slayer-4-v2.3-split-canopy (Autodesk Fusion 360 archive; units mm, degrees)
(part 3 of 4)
sketch "Sketch64" plane through (-29.64, 0, 0) normal (-1, 0, 0) x axis (0, -1, 0)
  line L1 (-15.4786, 27.5587) -> (-15.4786, 29.759)
  curve K1 (-15.4786, 27.5587) -> (-12.9624, 29.4655)
  curve K2 (-12.9624, 29.4655) -> (-5.541, 33.0818)
  curve K3 (-5.541, 33.0818) -> (-5, 33.1238)
  line L2 (-5, 34.5333) -> (-5, 33.1238)
  curve K4 (-5, 34.5333) -> (-5.9482, 34.4612)
  curve K5 (-5.9482, 34.4612) -> (-15.4786, 29.759)
  line L3 (0, 35) -> (0, 33.7692)
  line L4 (0, 33.7692) -> (0, 35)
  line L5 (-15.4786, 27.5587) -> (0, 30.4427)
  line L6 (0, 34.5333) -> (-5, 34.5333)
  line L7 (0, 30.4427) -> (0, 33.7692)
  point P10 (0, 35)
  point P11 (0, 35)
  point P9 (0, 33.7692)
  point P12 (0, 33.7692)
  point P3 (-15.4786, 27.5587)
  point P13 (-15.4786, 27.5587)
  point P7 (-5, 34.5333)
  point P14 (-5, 34.5333)
  point P15 (0, 34.5333)
  point P16 (0, 33.7692)
  coincident P10 P11
  coincident P9 P12
  coincident P3 P13
  coincident P7 P14
  coincident L3 P15
  perpendicular L3 L6
  coincident P9 P16
  parallel L3 L7
extrude "Extrude92" add sketch "Sketch64" against normal blind 1
fillet "Fillet171" radius 1
fillet "Fillet172" radius 1
sketch "Sketch65" plane through (0, 0, 0) normal (0, -1, 0) x axis (1, 0, 0)
  line L1 (-29.64, 34.7191) -> (-29.64, 33.3021)
  line L2 (-35.6561, 34.471) -> (-29.64, 34.7191)
  line L3 (-35.6561, 31.6426) -> (-35.6561, 34.471)
  line L4 (-32.8277, 28.8142) -> (-35.6561, 31.6426)
  line L5 (-31.4135, 30.2284) -> (-32.8277, 28.8142)
  line L6 (-29.64, 33.3021) -> (-31.4135, 30.2284)
  line L7 (-29.64, 30.2284) -> (-31.4135, 30.2284)
  line L8 (-29.64, 33.3021) -> (-29.64, 30.2284)
  point P7 (-31.4135, 30.2284)
  point P8 (-31.4135, 30.2284)
  point P2 (-29.64, 33.3021)
  point P10 (-29.64, 33.3021)
  coincident P7 P8
  horizontal L7
  coincident P2 P10
  perpendicular L7 L8
extrude "Extrude94" new body sketch "Sketch65" profile of L6 L7 L8 against normal blind 18.5
combine "Combine36"
remove_body "RemoveBody51"
combine "Combine37"
fillet "Fillet173" radius 9
fillet "Fillet174" radius 6
fillet "Fillet175" radius 2.2
sketch "Sketch66" plane through (0, 0, 0) normal (0, -1, 0) x axis (1, 0, 0)
  line L1 (-29.64, 34.7191) -> (-29.64, 30.2284)
  line L2 (-35.6561, 34.471) -> (-29.64, 34.7191)
  line L3 (-35.6561, 31.6426) -> (-35.6561, 34.471)
  line L4 (-32.8277, 28.8142) -> (-35.6561, 31.6426)
  line L5 (-32.0579, 29.584) -> (-32.8277, 28.8142)
  line L6 (-29.64, 30.2284) -> (-30.5022, 30.2284)
  line L7 (-29.14, 34.7191) -> (-29.64, 34.7191)
  line L8 (-29.64, 33.778) -> (-29.14, 34.7191)
  arc A1 centre (-30.5022, 28.0284) radius 2.2 clockwise from (-32.0579, 29.584) to (-30.5022, 30.2284)
  point P3 (-29.64, 34.7191)
  point P10 (-29.64, 34.7191)
  point P12 (-29.64, 33.778)
  point P11 (-29.14, 34.7191)
  coincident P3 P10
  perpendicular L1 L7
  coincident L1 P12
  dimension "d1042" distance P10 P11 = 0.5
extrude "Extrude95" add sketch "Sketch66" profile of L1 L7 L8 against normal blind 12.5
extrude "Extrude96" cut of existing geometry blind -2.5
mirror "Mirror18" mirrorStitchTolerance 0.1
fillet "Fillet99" radius 2
work_plane "WorkPlane9" AlongDistance -34
sketch "Sketch44" plane through (0, -34, 0) normal (0, 1, 0) x axis (1, 0, 0)
  line L1 (-22.45, -24) -> (-25.55, -24)
  line L2 (25.55, -19) -> (22.45, -19)
  line L3 (24, -9.5) -> (-24, -9.5)
  line L4 (-8, -9.5) -> (0, -9.5)
  line L5 (-8, -14.5) -> (-8, -9.5)
  line L6 (0, -14.5) -> (-8, -14.5)
  line L7 (0, -9.5) -> (0, -14.5)
  line L8 (8, -14.5) -> (-8, -14.5)
  line L9 (8, -2) -> (8, -14.5)
  line L10 (-8, -2) -> (8, -2)
  line L11 (-8, -14.5) -> (-8, -2)
  line L12 (-19.8891, -2) -> (-0.0223, -2)
  point P8 (0, -9.5)
  point P15 (-19.8891, -2)
  parallel L2 L3
  horizontal L4
  vertical L5
  horizontal L6
  vertical L7
  midpoint L3 P8
  horizontal L8
  vertical L9
  horizontal L10
  vertical L11
  coincident L10 P15
  dimension "d573" distance L5 L7 = 8
  dimension "d574" distance L4 L6 = 5
  dimension "d576" distance L7 L9 = 8 (= "d573")
component_insert "Component Insert7"
component_insert "Component Insert8"
joint "Assemble1" alignAngle -90 alignOffsetX 0 alignOffsetY 0 alignOffsetZ 0
joint "Assemble2" alignAngle 0 alignOffsetX 0 alignOffsetY 0 alignOffsetZ 0
joint "Assemble3" alignAngle -90 alignOffsetX 0 alignOffsetY 0 alignOffsetZ 0
joint "Assemble4" alignAngle 0 alignOffsetX 0 alignOffsetY 0 alignOffsetZ 0
joint "Assemble5" alignAngle 180 alignOffsetX 0 alignOffsetY 0 alignOffsetZ 0
component_insert "Component Insert9"
component_insert "Component Insert10"
component_insert "Component Insert11"
component_insert "Component Insert12"
component_insert "Component Insert13"
component_insert "Component Insert14"
fillet "Fillet130" radius 1.5
copy_paste "CutPaste2"
copy_paste "CutPaste3"
copy_paste "CutPaste4"
copy_paste "CutPaste5"
copy_paste "CutPaste6"
copy_paste "CutPaste7"
copy_paste "CutPaste8"
copy_paste "CutPaste9"
copy_paste "CutPaste10"
copy_paste "CutPaste11"
copy_paste "CutPaste12"
copy_paste "CutPaste13"
copy_paste "CutPaste14"
joint "Assemble8" alignAngle 0 alignOffsetX 0 alignOffsetY 0 alignOffsetZ 0
joint "Assemble9" alignAngle 0 alignOffsetX 0 alignOffsetY 0 alignOffsetZ 0
as_built_joint "As-built1"
as_built_joint "As-built2"
as_built_joint "As-built3"
as_built_joint "As-built4"
joint "Assemble10" alignAngle -50 alignOffsetX 0 alignOffsetY 0 alignOffsetZ 0
joint "Assemble11" alignAngle 40 alignOffsetX 0 alignOffsetY 0 alignOffsetZ 0
joint "Assemble12" alignAngle -50 alignOffsetX 0 alignOffsetY 0 alignOffsetZ 0
joint "Assemble13" alignAngle -40 alignOffsetX 0 alignOffsetY 0 alignOffsetZ 0
copy_paste "CutPaste16"
copy_paste_bodies "CopyPasteBodies1"
move "Move1" RotateAngle 10
component_insert "Component Insert1"
extrude "Extrude1" add of existing geometry blind -6
sketch "cam-mount-standoff" plane through (0, 0, 2) normal (0, 0, 1) x axis (-1, 0, 0)
  line L1 (-29.0384, -18.7057) -> (-35.3306, -4.3323)
  line L2 (-7.8768, -19.0795) -> (-10.419, -18.9098)
  line L3 (10.419, -18.9098) -> (7.8768, -19.0795)
  line L4 (7.8768, 19.0795) -> (10.419, 18.9098)
  line L5 (-10.419, 18.9098) -> (-7.8768, 19.0795)
  line L6 (-35.3306, 4.3323) -> (-29.0384, 18.7057)
  line L7 (-35.4985, -3.5303) -> (-35.4985, 3.5303)
  line L8 (-30.099, -8.8021) -> (-29.2912, -10.6474)
  line L9 (-24.7203, -6) -> (-28.2669, -6)
  line L10 (-28.2669, 6) -> (-24.7203, 6)
  line L11 (-29.2912, 10.6474) -> (-30.099, 8.8021)
  line L12 (-30.4985, -3) -> (-23.0892, -3)
  line L13 (-32.4985, 1) -> (-32.4985, -1)
  line L14 (-23.0892, 3) -> (-30.4985, 3)
  line L15 (15.3479, -5.782) -> (13.4133, -8.1699)
  line L16 (19.6919, -8.9044) -> (18.7852, -6.3678)
  line L17 (13.4936, -15.6979) -> (15.3167, -15.5763)
  line L18 (13.4133, 8.1699) -> (15.3479, 5.782)
  line L19 (15.3167, 15.5763) -> (13.4936, 15.6979)
  line L20 (18.7852, 6.3678) -> (19.6919, 8.9044)
  line L21 (-15.3479, 5.782) -> (-13.4133, 8.1699)
  line L22 (-19.6919, 8.9044) -> (-18.7852, 6.3678)
  line L23 (-13.4936, 15.6979) -> (-15.3167, 15.5763)
  line L24 (-13.4133, -8.1699) -> (-15.3479, -5.782)
  line L25 (-15.3167, -15.5763) -> (-13.4936, -15.6979)
  line L26 (-18.7852, -6.3678) -> (-19.6919, -8.9044)
  line L27 (18.0216, 10.02) -> (29.5161, 10.02)
  line L28 (22.8958, 10.02) -> (20.2338, 13.9469)
  line L29 (36.0628, 10.02) -> (27.3627, 19.565)
  line L30 (40.7792, 10.02) -> (29.5161, 10.02)
  line L31 (28.5286, 16.0592) -> (34.0332, 10.02)
  line L32 (23.37, 11.9938) -> (24.708, 10.02)
  line L33 (32.3778, 13.0107) -> (38.3863, 7.4856)
  line L34 (22.1379, -6.8345) -> (22.6368, -8.2301)
  line L35 (22.6368, 8.2301) -> (22.1379, 6.8345)
  arc A1 centre (-33.4985, -3.5303) radius 2 clockwise from (-35.3306, -4.3323) to (-35.4985, -3.5303)
  arc A2 centre (-24, -16.5) radius 5.5 clockwise from (-21.3581, -21.3239) to (-29.0384, -18.7057)
  arc A3 centre (-11.751, -38.8654) radius 20 clockwise from (-21.3581, -21.3239) to (-10.419, -18.9098)
  arc A4 centre (-9.0756, -37.0396) radius 18 clockwise from (-7.8768, -19.0795) to (-1.2965, -20.8073)
  arc A5 centre (0, -18.1019) radius 3 clockwise from (1.2965, -20.8073) to (-1.2965, -20.8073)
  arc A6 centre (9.0756, -37.0396) radius 18 clockwise from (1.2965, -20.8073) to (7.8768, -19.0795)
  arc A7 centre (11.751, -38.8654) radius 20 clockwise from (10.419, -18.9098) to (21.3581, -21.3239)
  arc A8 centre (24, -16.5) radius 5.5 clockwise from (25.7522, -11.2866) to (21.3581, -21.3239)
  arc A9 centre (24, 16.5) radius 5.5 clockwise from (21.3581, 21.3239) to (25.7522, 11.2866)
  arc A10 centre (11.751, 38.8654) radius 20 clockwise from (21.3581, 21.3239) to (10.419, 18.9098)
  arc A11 centre (9.0756, 37.0396) radius 18 clockwise from (7.8768, 19.0795) to (1.2965, 20.8073)
  arc A12 centre (0, 18.1019) radius 3 clockwise from (-1.2965, 20.8073) to (1.2965, 20.8073)
  arc A13 centre (-9.0756, 37.0396) radius 18 clockwise from (-1.2965, 20.8073) to (-7.8768, 19.0795)
  arc A14 centre (-11.751, 38.8654) radius 20 clockwise from (-10.419, 18.9098) to (-21.3581, 21.3239)
  arc A15 centre (-24, 16.5) radius 5.5 clockwise from (-29.0384, 18.7057) to (-21.3581, 21.3239)
  arc A16 centre (-33.4985, 3.5303) radius 2 clockwise from (-35.4985, 3.5303) to (-35.3306, 4.3323)
  arc A17 centre (-28.2669, -8) radius 2 clockwise from (-30.099, -8.8021) to (-28.2669, -6)
  arc A18 centre (-27.4591, -9.8453) radius 2 clockwise from (-26.5366, -11.6199) to (-29.2912, -10.6474)
  arc A19 centre (-28.2669, 8) radius 2 clockwise from (-28.2669, 6) to (-30.099, 8.8021)
  arc A20 centre (-27.4591, 9.8453) radius 2 clockwise from (-29.2912, 10.6474) to (-26.5366, 11.6199)
  arc A21 centre (-30.4985, -1) radius 2 clockwise from (-30.4985, -3) to (-32.4985, -1)
  arc A22 centre (-30.4985, 1) radius 2 clockwise from (-32.4985, 1) to (-30.4985, 3)
  circle C1 centre (18.1019, 0) radius 1.05
  circle C2 centre (24, -16.5) radius 1.55
  arc A23 centre (16.9019, -7.041) radius 2 clockwise from (15.3479, -5.782) to (18.7852, -6.3678)
  arc A24 centre (14.9837, -10.5874) radius 5 clockwise from (19.6919, -8.9044) to (15.3167, -15.5763)
  arc A25 centre (13.3604, -13.7024) radius 2 clockwise from (13.4936, -15.6979) to (12.0163, -12.2214)
  arc A26 centre (10, -10) radius 3 clockwise from (12.9804, -9.6573) to (12.0163, -12.2214)
  arc A27 centre (14.9673, -9.4289) radius 2 clockwise from (12.9804, -9.6573) to (13.4133, -8.1699)
  circle C3 centre (10, -10) radius 1.05
  circle C4 centre (10, 10) radius 1.05
  arc A28 centre (14.9673, 9.4289) radius 2 clockwise from (13.4133, 8.1699) to (12.9804, 9.6573)
  arc A29 centre (10, 10) radius 3 clockwise from (12.0163, 12.2214) to (12.9804, 9.6573)
  arc A30 centre (13.3604, 13.7024) radius 2 clockwise from (12.0163, 12.2214) to (13.4936, 15.6979)
  arc A31 centre (14.9837, 10.5874) radius 5 clockwise from (15.3167, 15.5763) to (19.6919, 8.9044)
  arc A32 centre (16.9019, 7.041) radius 2 clockwise from (18.7852, 6.3678) to (15.3479, 5.782)
  circle C5 centre (24, 16.5) radius 1.55
  circle C6 centre (-24, 16.5) radius 1.55
  arc A33 centre (-16.9019, 7.041) radius 2 clockwise from (-15.3479, 5.782) to (-18.7852, 6.3678)
  arc A34 centre (-14.9837, 10.5874) radius 5 clockwise from (-19.6919, 8.9044) to (-15.3167, 15.5763)
  arc A35 centre (-13.3604, 13.7024) radius 2 clockwise from (-13.4936, 15.6979) to (-12.0163, 12.2214)
  arc A36 centre (-10, 10) radius 3 clockwise from (-12.9804, 9.6573) to (-12.0163, 12.2214)
  arc A37 centre (-14.9673, 9.4289) radius 2 clockwise from (-12.9804, 9.6573) to (-13.4133, 8.1699)
  circle C7 centre (-10, 10) radius 1.05
  circle C8 centre (-10, -10) radius 1.05
  arc A38 centre (-14.9673, -9.4289) radius 2 clockwise from (-13.4133, -8.1699) to (-12.9804, -9.6573)
  arc A39 centre (-10, -10) radius 3 clockwise from (-12.0163, -12.2214) to (-12.9804, -9.6573)
  arc A40 centre (-13.3604, -13.7024) radius 2 clockwise from (-12.0163, -12.2214) to (-13.4936, -15.6979)
  arc A41 centre (-14.9837, -10.5874) radius 5 clockwise from (-15.3167, -15.5763) to (-19.6919, -8.9044)
  arc A42 centre (-16.9019, -7.041) radius 2 clockwise from (-18.7852, -6.3678) to (-15.3479, -5.782)
  circle C9 centre (-24, -16.5) radius 1.55
  circle C10 centre (-18.1019, 0) radius 1.05
  circle C11 centre (0, -18.1019) radius 1.05
  circle C12 centre (0, 18.1019) radius 1.05
  arc A43 centre (0, 3.3668) radius 9 clockwise from (-7.5, 8.3417) to (7.5, 8.3417)
  arc A44 centre (10, 10) radius 3 clockwise from (8.3417, 7.5) to (7.5, 8.3417)
  arc A45 centre (3.3668, 0) radius 9 clockwise from (8.3417, 7.5) to (8.3417, -7.5)
  arc A46 centre (10, -10) radius 3 clockwise from (7.5, -8.3417) to (8.3417, -7.5)
  arc A47 centre (0, -3.3668) radius 9 clockwise from (7.5, -8.3417) to (-7.5, -8.3417)
  arc A48 centre (-10, -10) radius 3 clockwise from (-8.3417, -7.5) to (-7.5, -8.3417)
  arc A49 centre (-3.3668, 0) radius 9 clockwise from (-8.3417, -7.5) to (-8.3417, 7.5)
  arc A50 centre (-10, 10) radius 3 clockwise from (-7.5, 8.3417) to (-8.3417, 7.5)
  circle C13 centre (24, 16.5) radius 3.05
  circle C14 centre (24, 16.5) radius 4.55
  arc A51 centre (27.345, -6.5471) radius 5 clockwise from (25.7522, -11.2866) to (22.6368, -8.2301)
  arc A52 centre (39.0876, -0.7757) radius 18 clockwise from (22.1379, -6.8345) to (21.0999, -0.1108)
  arc A53 centre (18.1019, 0) radius 3 clockwise from (21.0999, 0.1108) to (21.0999, -0.1108)
  arc A54 centre (39.0876, 0.7757) radius 18 clockwise from (21.0999, 0.1108) to (22.1379, 6.8345)
  arc A55 centre (27.345, 6.5471) radius 5 clockwise from (22.6368, 8.2301) to (25.7522, 11.2866)
  arc A56 centre (-24, 16.5) radius 5.5 clockwise from (-25.7522, 11.2866) to (-26.5366, 11.6199)
  arc A57 centre (-27.345, 6.5471) radius 5 clockwise from (-25.7522, 11.2866) to (-22.9705, 8.9686)
  arc A58 centre (-24.7203, 8) radius 2 clockwise from (-22.9705, 8.9686) to (-24.7203, 6)
  arc A59 centre (-24.7203, -8) radius 2 clockwise from (-24.7203, -6) to (-22.9705, -8.9686)
  arc A60 centre (-27.345, -6.5471) radius 5 clockwise from (-22.9705, -8.9686) to (-25.7522, -11.2866)
  arc A61 centre (-24, -16.5) radius 5.5 clockwise from (-26.5366, -11.6199) to (-25.7522, -11.2866)
  arc A62 centre (-39.0876, 0.7757) radius 18 clockwise from (-21.0894, 1.028) to (-21.0999, 0.1108)
  arc A63 centre (-18.1019, 0) radius 3 clockwise from (-21.0999, -0.1108) to (-21.0999, 0.1108)
  arc A64 centre (-39.0876, -0.7757) radius 18 clockwise from (-21.0999, -0.1108) to (-21.0894, -1.028)
  arc A65 centre (-23.0892, -1) radius 2 clockwise from (-21.0894, -1.028) to (-23.0892, -3)
  arc A66 centre (-23.0892, 1) radius 2 clockwise from (-23.0892, 3) to (-21.0894, 1.028)
  point P134 (22.8958, 10.02)
  point P131 (29.5161, 10.02)
  point P137 (29.5161, 10.02)
  point P136 (36.0628, 10.02)
  point P139 (34.0332, 10.02)
  point P141 (24.708, 10.02)
  point P133 (20.2338, 13.9469)
  point P142 (23.37, 11.9938)
  point P135 (27.3627, 19.565)
  point P140 (28.5286, 16.0592)
  concentric A9 C13
  coincident L27 P134
  coincident P131 P137
  parallel L27 L30
  coincident P136 L30
  coincident L30 P139
  parallel L29 L31
  parallel L28 L32
  coincident L27 P141
  concentric A9 C14
  coincident P133 C14
  tangent L28 C14
  coincident P142 C14
  coincident P135 C14
  tangent L29 C14
  coincident P140 C14
  dimension "d824" diameter C13 = 6.1 (= "( 3.05 * 2 ) * 1 mm")
  dimension "d833" distance L29 L31 = 1.5
  dimension "d834" distance L28 L32 = 1.5
  dimension "d836" distance C13 C14 = 1.5
sketch "cam-mount-skirt" plane through (0, 0, -5) normal (0, 0, 1) x axis (-1, 0, 0)
  line L1 (32.3778, 13.0107) -> (38.3863, 7.4856)
  line L2 (10.5918, 15.9571) -> (11.8125, 16.192)
  line L3 (-9.4583, 15.8491) -> (9.4583, 15.8491)
  line L4 (-11.8125, 16.192) -> (-10.5918, 15.9571)
  line L5 (-25.5, -3.8608) -> (-25.5, 3.8608)
  line L6 (-10.5918, -15.9571) -> (-11.8125, -16.192)
  line L7 (9.4583, -15.8491) -> (-9.4583, -15.8491)
  line L8 (11.8125, -16.192) -> (10.5918, -15.9571)
  line L9 (38.3863, -7.4856) -> (32.3778, -13.0107)
  line L10 (40.0019, 3.8052) -> (40.0019, -3.8052)
  line L11 (30.4401, -6) -> (28.2365, -6)
  line L12 (30.229, -10.9111) -> (31.7938, -9.4722)
  line L13 (25.5, 1) -> (25.5, -1)
  line L14 (35.0019, 3) -> (27.5, 3)
  line L15 (37.0019, -1) -> (37.0019, 1)
  line L16 (27.5, -3) -> (35.0019, -3)
  line L17 (-1.1558, 6.9329) -> (-3.1469, 10.7087)
  line L18 (-8.485, 4) -> (-2.9249, 4)
  curve K1 (-19.3632, 20.3456) -> (-19.8418, 20.8254)
  curve K2 (-10.0564, 11.7767) -> (-11.9135, 8.8933)
  line L19 (-4.916, 11.7757) -> (-9.9931, 11.7757)
  curve K3 (10.0564, 11.7767) -> (11.9135, 8.8933)
  curve K4 (19.3632, 20.3456) -> (19.8418, 20.8254)
  line L20 (1.2286, 8.8428) -> (3.2198, 5.0671)
  line L21 (2.9977, -11.7757) -> (9.9931, -11.7757)
  line L22 (3.2198, -5.0671) -> (1.2286, -8.8428)
  line L23 (8.485, -4) -> (4.9888, -4)
  curve K5 (19.3632, -20.3456) -> (19.8418, -20.8254)
  curve K6 (10.0564, -11.7767) -> (11.9135, -8.8933)
  line L24 (-3.1469, -10.7087) -> (-1.1558, -6.9329)
  line L25 (-9.9931, -11.7757) -> (-4.916, -11.7757)
  curve K7 (-10.0564, -11.7767) -> (-11.9135, -8.8933)
  curve K8 (-19.3632, -20.3456) -> (-19.8418, -20.8254)
  line L26 (-2.9249, -4) -> (-8.485, -4)
  curve K9 (15, 0) -> (19.2416, 6.0748)
  curve K10 (19.2416, 6.0748) -> (22.5, 4.5203)
  line L27 (22.5, -4.5203) -> (22.5, 4.5203)
  curve K11 (19.2416, -6.0748) -> (22.5, -4.5203)
  curve K12 (15, 0) -> (19.2416, -6.0748)
  line L28 (-22.5, 4.5203) -> (-22.5, -4.5203)
  curve K13 (-19.2416, 6.0748) -> (-22.5, 4.5203)
  curve K14 (-15, 0) -> (-19.2416, 6.0748)
  curve K15 (-15, 0) -> (-19.2416, -6.0748)
  curve K16 (-19.2416, -6.0748) -> (-22.5, -4.5203)
  line L29 (28.2365, 6) -> (30.4401, 6)
  line L30 (31.7938, 9.4722) -> (30.229, 10.9111)
  line L31 (35.8754, 11.8323) -> (41.5019, 6.6585)
  line L32 (41.5019, 6.6585) -> (41.5019, 0)
  line L33 (34.8601, 10.7281) -> (35.8754, 11.8323)
  line L34 (40.0019, 0) -> (41.5019, 0)
  curve K17 (19.3632, 20.3456) -> (11.8125, 16.192)
  curve K18 (-19.3632, 20.3456) -> (-11.8125, 16.192)
  curve K19 (-19.3632, -20.3456) -> (-11.8125, -16.192)
  curve K20 (19.3632, -20.3456) -> (11.8125, -16.192)
  curve K21 (10.3646, -5.3164) -> (8.485, -4)
  curve K22 (10.3646, -5.3164) -> (11.9135, -8.8933)
  curve K23 (9.9931, -11.7757) -> (10.0564, -11.7767)
  curve K24 (-9.9931, -11.7757) -> (-10.0564, -11.7767)
  curve K25 (-10.3646, -5.3164) -> (-11.9135, -8.8933)
  curve K26 (-8.485, -4) -> (-10.3646, -5.3164)
  curve K27 (-8.485, 4) -> (-10.3646, 5.3164)
  curve K28 (-10.3646, 5.3164) -> (-11.9135, 8.8933)
  curve K29 (-9.9931, 11.7757) -> (-10.0564, 11.7767)
  line L35 (9.9931, 11.7757) -> (2.9977, 11.7757)
  curve K30 (9.9931, 11.7757) -> (10.0564, 11.7767)
  curve K31 (10.3646, 5.3164) -> (11.9135, 8.8933)
  curve K32 (10.3646, 5.3164) -> (8.485, 4)
  line L36 (4.9888, 4) -> (8.485, 4)
  arc A1 centre (35.0019, 3.8052) radius 5 clockwise from (38.3863, 7.4856) to (40.0019, 3.8052)
  arc A2 centre (37.7928, 18.8995) radius 8 clockwise from (32.3778, 13.0107) to (29.9112, 17.5284)
  arc A3 centre (24, 16.5) radius 6 clockwise from (19.8418, 20.8254) to (29.9112, 17.5284)
  arc A4 centre (9.4583, 21.8491) radius 6 clockwise from (10.5918, 15.9571) to (9.4583, 15.8491)
  arc A5 centre (-9.4583, 21.8491) radius 6 clockwise from (-9.4583, 15.8491) to (-10.5918, 15.9571)
  arc A6 centre (-24, 16.5) radius 6 clockwise from (-28.65, 12.7082) to (-19.8418, 20.8254)
  arc A7 centre (-24, -16.5) radius 6 clockwise from (-19.8418, -20.8254) to (-28.65, -12.7082)
  arc A8 centre (-9.4583, -21.8491) radius 6 clockwise from (-10.5918, -15.9571) to (-9.4583, -15.8491)
  arc A9 centre (9.4583, -21.8491) radius 6 clockwise from (9.4583, -15.8491) to (10.5918, -15.9571)
  arc A10 centre (24, -16.5) radius 6 clockwise from (29.9112, -17.5284) to (19.8418, -20.8254)
  arc A11 centre (37.7928, -18.8995) radius 8 clockwise from (29.9112, -17.5284) to (32.3778, -13.0107)
  arc A12 centre (35.0019, -3.8052) radius 5 clockwise from (40.0019, -3.8052) to (38.3863, -7.4856)
  arc A13 centre (30.4401, -8) radius 2 clockwise from (30.4401, -6) to (31.7938, -9.4722)
  arc A14 centre (27.5, 1) radius 2 clockwise from (25.5, 1) to (27.5, 3)
  arc A15 centre (35.0019, 1) radius 2 clockwise from (35.0019, 3) to (37.0019, 1)
  arc A16 centre (35.0019, -1) radius 2 clockwise from (37.0019, -1) to (35.0019, -3)
  arc A17 centre (27.5, -1) radius 2 clockwise from (27.5, -3) to (25.5, -1)
  circle C1 centre (24, 16.5) radius 1.55
  circle C2 centre (-24, 16.5) radius 1.55
  arc A18 centre (-2.9249, 6) radius 2 clockwise from (-1.1558, 6.9329) to (-2.9249, 4)
  arc A19 centre (-4.916, 9.7757) radius 2 clockwise from (-4.916, 11.7757) to (-3.1469, 10.7087)
  arc A20 centre (4.9888, 6) radius 2 clockwise from (4.9888, 4) to (3.2198, 5.0671)
  arc A21 centre (2.9977, 9.7757) radius 2 clockwise from (1.2286, 8.8428) to (2.9977, 11.7757)
  arc A22 centre (2.9977, -9.7757) radius 2 clockwise from (2.9977, -11.7757) to (1.2286, -8.8428)
  arc A23 centre (4.9888, -6) radius 2 clockwise from (3.2198, -5.0671) to (4.9888, -4)
  arc A24 centre (-4.916, -9.7757) radius 2 clockwise from (-3.1469, -10.7087) to (-4.916, -11.7757)
  arc A25 centre (-2.9249, -6) radius 2 clockwise from (-2.9249, -4) to (-1.1558, -6.9329)
  circle C3 centre (-24, -16.5) radius 1.55
  circle C4 centre (24, -16.5) radius 1.55
  arc A26 centre (30.4401, 8) radius 2 clockwise from (31.7938, 9.4722) to (30.4401, 6)
  arc A27 centre (-39.5, 3.8608) radius 14 clockwise from (-28.65, 12.7082) to (-25.5, 3.8608)
  arc A28 centre (-39.5, -3.8608) radius 14 clockwise from (-25.5, -3.8608) to (-28.65, -12.7082)
  arc A29 centre (28.8753, -9.4389) radius 2 clockwise from (30.229, -10.9111) to (27.1045, -10.3686)
  arc A30 centre (39.5, -3.8608) radius 14 clockwise from (27.1045, -10.3686) to (26.3592, -8.6899)
  arc A31 centre (28.2365, -8) radius 2 clockwise from (26.3592, -8.6899) to (28.2365, -6)
  arc A32 centre (28.2365, 8) radius 2 clockwise from (28.2365, 6) to (26.3592, 8.6899)
  arc A33 centre (39.5, 3.8608) radius 14 clockwise from (26.3592, 8.6899) to (27.1045, 10.3686)
  arc A34 centre (28.8753, 9.4389) radius 2 clockwise from (27.1045, 10.3686) to (30.229, 10.9111)
  point P115 (41.5019, 6.6585)
  point P116 (41.5019, 6.6585)
  point P117 (34.8601, 10.7281)
  point P118 (40.0019, 0)
  coincident P115 P116
  coincident L1 P117
  perpendicular L1 L33
  midpoint L10 P118
  perpendicular L10 L34
  dimension "d828" distance L1 L31 = 1.5
  dimension "d829" distance L10 L32 = 1.5
extrude "Extrude2" new body sketch "cam-mount-standoff" profile of A9 A10 C13 L27 L28 L29 L30 L31 L32 C14 along normal blind 26.3
base_feature "Base Feature1" bodies "top (1)"
move "Move2"
move "Move1"
work_plane "WorkPlane1" AlongDistance 7
work_plane "WorkPlane2" AlongDistance -22.896 (= "-23.00 mm + 0.104 mm")
extrude "Extrude3" add of existing geometry blind 16
split "Split1" bodies "cam-mount-shell (1)"
split "Split2" bodies "cam-mount-shell (2)"
position "Position10"
sketch "Sketch3" plane through (0, 0, 7) normal (0, 0, -1) x axis (1, 0, 0)
  line L1 (-41.2228, 11.52) -> (-22.896, 11.52)
  line L2 (-41.2228, 0) -> (-41.2228, 11.52)
  line L3 (-38.6076, 0) -> (-41.2228, 0)
  line L4 (-38.6076, 10.02) -> (-38.6076, 0)
  line L5 (-22.896, 10.02) -> (-38.6076, 10.02)
  line L6 (-22.896, 11.52) -> (-22.896, 10.02)
  line L7 (-39.7228, 10.02) -> (-38.6076, 10.02)
  line L8 (-39.7228, 0) -> (-39.7228, 10.02)
  point P6 (-38.6076, 10.02)
  point P8 (-38.6076, 10.02)
  point P10 (-39.7228, 0)
  coincident P6 P8
  perpendicular L4 L7
  coincident L3 P10
  perpendicular L3 L8
  dimension "d841" distance L2 L8 = 1.5
extrude "Extrude4" cut sketch "Sketch3" profile of L3 L4 L7 L8 against normal blind 2.5
extrude "Extrude5" add of existing geometry blind 5
chamfer "Chamfer1" distance 2
sketch "Sketch4" plane through (0, 0, 28.3) normal (0, 0, 1) x axis (-1, 0, 0)
  line L1 (34.2399, 12.02) -> (32.2103, 12.02)
  line L2 (27.3627, 19.565) -> (34.2399, 12.02)
  line L3 (22.8958, 10.02) -> (20.2338, 13.9469)
  line L4 (24.708, 10.02) -> (22.8958, 10.02)
  line L5 (23.37, 11.9938) -> (24.708, 10.02)
  line L6 (32.2103, 12.02) -> (28.5286, 16.0592)
  line L7 (21.4754, 14.7886) -> (23.37, 11.9938)
  line L8 (26.2541, 18.5546) -> (28.5286, 16.0592)
  line L9 (20.2338, 13.9469) -> (21.4754, 14.7886)
  arc A1 centre (24, 16.5) radius 4.55 clockwise from (20.2338, 13.9469) to (27.3627, 19.565)
  arc A2 centre (24, 16.5) radius 4.55 clockwise from (28.5286, 16.0592) to (23.37, 11.9938)
  circle C1 centre (24, 16.5) radius 3.05
  point P9 (23.37, 11.9938)
  point P11 (23.37, 11.9938)
  point P12 (21.4754, 14.7886)
  point P10 (28.5286, 16.0592)
  point P13 (28.5286, 16.0592)
  point P14 (26.2541, 18.5546)
  point P5 (20.2338, 13.9469)
  point P15 (20.2338, 13.9469)
  coincident P9 P11
  coincident C1 P12
  tangent C1 L7
  coincident P10 P13
  coincident C1 P14
  tangent C1 L8
  coincident P5 P15
extrude "Extrude6" cut sketch "Sketch4" profile of A2 C1 L7 L8 against normal blind 46
extrude "Extrude7" cut sketch "Sketch4" profile of L3 L4 L5 L7 L9 against normal blind 6
sketch "Sketch5" plane through (0, 0, 2) normal (0, 0, -1) x axis (1, 0, 0)
  line L1 (-22.896, 10.02) -> (-39.7228, 10.02)
  line L2 (-22.896, 11.52) -> (-22.896, 10.02)
  line L3 (-41.2228, 11.52) -> (-22.896, 11.52)
  line L4 (-41.2228, 0) -> (-41.2228, 11.52)
  line L5 (-39.7228, 0) -> (-41.2228, 0)
  line L6 (-39.7228, 10.02) -> (-39.7228, 0)
  line L7 (-34.8601, 10.7281) -> (-35.8754, 11.8323)
  line L8 (-34.209, 10.02) -> (-34.8601, 10.7281)
  line L9 (-36.2248, 12.2122) -> (-35.8754, 11.8323)
  point P9 (-34.8601, 10.7281)
  point P10 (-34.8601, 10.7281)
  point P11 (-34.209, 10.02)
  point P8 (-35.8754, 11.8323)
  point P12 (-35.8754, 11.8323)
  coincident P9 P10
  coincident L1 P11
  parallel L7 L8
  coincident P8 P12
  parallel L7 L9
extrude "Extrude8" cut sketch "Sketch5" profile of L1 L3 L4 L5 L6 L7 L8 L9 against normal blind 5
combine "Combine1" bodies "cam-mount-shell (2)"
loft "Loft1" sketch "cam-mount-skirt"
fillet "Fillet1" radius 3
fillet "Fillet2" radius 2
fillet "Fillet3" radius 1
fillet "Fillet4" radius 2
fillet "Fillet5" radius 2
fillet "Fillet6" radius 1
chamfer "Chamfer2" distance 1
chamfer "Chamfer3" distance 2
chamfer "Chamfer4" distance 1
fillet "Fillet10" radius 1
component_insert "Component Insert2"
sketch "Sketch7" plane through (0, -10.02, 0) normal (0, 1, 0) x axis (-1, 0, 0)
  curve K1 (33.4338, 2) -> (34.0973, 7)
  line L1 (34.0973, 7) -> (34.209, 7)
  line L2 (35.4854, 7) -> (34.209, 7)
  line L3 (39.7228, 7.7809) -> (39.7228, 7)
  line L4 (43.1065, 10.1501) -> (39.7228, 7.7809)
  line L5 (36.0628, 20.2095) -> (43.1065, 10.1501)
  line L6 (34.0332, 23.1081) -> (36.0628, 20.2095)
  line L7 (22.896, 20.4629) -> (31.612, 26.566)
  line L8 (22.896, 22.2941) -> (22.896, 20.4629)
  line L9 (22.8958, 22.3) -> (22.9044, 22.3)
  line L10 (22.8958, 2) -> (22.8958, 22.3)
  line L11 (33.4338, 2) -> (22.8958, 2)
  curve K2 (33.26, 14.3566) -> (32.1953, 15.8771)
  line L12 (39.7228, 7) -> (35.4854, 7)
  line L13 (22.9044, 22.3) -> (22.896, 22.2941)
  line L14 (31.612, 26.566) -> (34.0332, 23.1081)
  arc A1 centre (32.9724, 15.2882) radius 0.975 clockwise from (33.26, 14.3566) to (32.1953, 15.8771)
extrude "Extrude9" cut sketch "Sketch7" profile of K2 A1 against normal blind 10.5
sketch "Sketch8" plane through (0, -11.52, 0) normal (0, -1, 0) x axis (1, 0, 0)
  curve K1 (-35.5375, 7) -> (-34.9976, 2)
  line L1 (-34.6956, 2) -> (-34.9976, 2)
  line L2 (-34.6956, 22.6295) -> (-34.6956, 2)
  curve K2 (-34.6956, 22.6295) -> (-44.2989, 9.154)
  line L3 (-41.2228, 7) -> (-44.2989, 9.154)
  line L4 (-35.5375, 7) -> (-35.5883, 7)
  curve K3 (-32.1953, 15.8771) -> (-33.26, 14.3566)
  line L5 (-36.1672, 7) -> (-41.2228, 7)
  line L6 (-35.5883, 7) -> (-36.1672, 7)
  arc A1 centre (-32.9724, 15.2882) radius 0.975 clockwise from (-32.1953, 15.8771) to (-33.26, 14.3566)
  circle C1 centre (-32.9724, 15.2882) radius 2.65
  concentric A1 C1
  dimension "d874" diameter C1 = 5.3
extrude "Extrude10" cut sketch "Sketch8" profile of L2 A1 K3 C1 along normal blind 8.5
fillet "Fillet8" radius 3
fillet "Fillet11" radius 0.5
extrude "Extrude11" add of existing geometry blind 2
fillet "Fillet9" radius 5
mirror "Mirror1" mirrorStitchTolerance 0.1
position "Position9"
position "Position8"
position "Position6"
position "Position7"
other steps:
base_feature "Base Feature1" bodies "cam-mount-shell"
base_feature "Base Feature4"
base_feature "Base Feature3"
base_feature "Base Feature2"
joint_origin "JointOrigin4"
create_component "CreateComponent2"
remove_instance "RemoveInstance2"
remove_instance "RemoveInstance3"
remove_instance "RemoveInstance4"
remove_instance "RemoveInstance5"
remove_instance "RemoveInstance6"
remove_instance "RemoveInstance7"
remove_instance "RemoveInstance8"
remove_instance "RemoveInstance9"
remove_instance "RemoveInstance10"
remove_instance "RemoveInstance11"
remove_instance "RemoveInstance12"
remove_instance "RemoveInstance13"
remove_instance "RemoveInstance14"
joint_origin "JointOrigin7"
joint_origin "JointOrigin8"
joint_origin "JointOrigin9"
joint_origin "JointOrigin10"
create_component "CreateComponent3"
remove_instance "RemoveInstance16"
create_component "CreateComponent1"
joint_origin "JointOrigin11"
joint_origin "JointOrigin12"
named bodies: "center-upper", "arm-fl", "arm-rr", "arm-rl", "cam-mount-shell", "canopy", "cam-mount-shell (1)", "cam-mount-35", "top (1)", "cam-mount-shell (2)", "puzzle", "arm-fr", "center-lower", "canopy-cam", "canopy (1) (2)", "canopy (1) (1) (1)", "canopy (1)", "canopy-tail", "canopy-cam (2)", "canopy-cam (3)", "canopy-cam (1) (1)", "canopy-cam (1) (1) (1)"

design "20x20 Flight Controller"
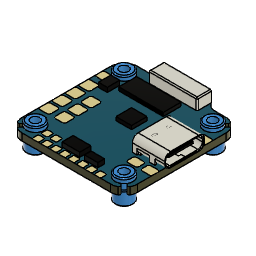
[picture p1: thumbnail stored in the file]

design "Slayer Hurricane 4040"
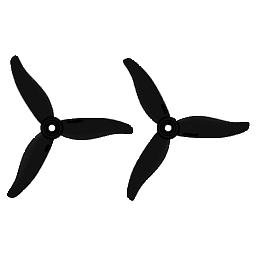
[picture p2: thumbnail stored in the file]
sketch "Sketch1" plane through (0, 0, 0) normal (0, 1, 0) x axis (1, 0, 0)
  curve K1 (5.4694, -4.0404) -> (5.1621, 4.4263)
  curve K2 (23.4739, 6.387) -> (7.3147, 5.303)
  curve K3 (43.581, 4.1632) -> (31.5201, 5.982)
  curve K4 (18.3421, -7.4304) -> (33.5067, -4.4448)
  curve K5 (4.6655, -5.2742) -> (19.2218, -7.6881)
  curve K6 (39.69, -3.7559) -> (54.3074, -3.2468)
  curve K7 (53.947, -7.3026) -> (46.4681, 7.5356)
  curve K8 (51.5, 0) -> (44.2123, 4.0129)
  line L1 (78.7648, 0) -> (0, 0)
  curve K9 (47.845, -5.7624) -> (53.4117, -0.1713)
  curve K10 (8.9395, 5.261) -> (1.3848, 3.5917)
  circle C1 centre (0, 0) radius 6.8
  circle C2 centre (0, 0) radius 2.5
  circle C3 centre (0, 0) radius 50.8
  point P1 (0, 0)
  point P2 (0, 0)
  point P3 (0, 0)
  point P4 (5.1621, 4.4263)
  point P14 (5.4694, -4.0404)
  point P5 (15.3943, 5.845)
  point P6 (37.5505, 5.0726)
  point P12 (25.9244, -5.9376)
  point P13 (11.9437, -6.4811)
  point P10 (46.9987, -3.5013)
  point P8 (50.2076, 0.1165)
  point P7 (47.8561, 2.0065)
  point P29 (0, 0)
  point P9 (50.6284, -2.9668)
  coincident P1 P2
  coincident P1 P3
  coincident C1 P4
  coincident C1 P14
  midpoint P5 K2
  midpoint P6 K3
  midpoint P12 K4
  midpoint P13 K5
  midpoint P10 K6
  midpoint P8 K7
  midpoint P7 K8
  coincident P1 P29
  midpoint P9 K9
  midpoint P4 K10
  concentric C2 C3
  dimension "d1" diameter C1 = 13.6
  dimension "d2" diameter C2 = 5
  dimension "d78" diameter C3 = 101.6 (= "4")
extrude "Extrude1" new body sketch "Sketch1" profile of C1 C2 distance 7
work_plane "WorkPlane6" AlongDistance 4.5
sketch "Sketch3" plane through (4.5, 0, 0) normal (1, 0, 0) x axis (0, 0, -1)
  line L1 (6.8, -3.5) -> (-6.8, -3.5)
  line L2 (-6.8, 3.5) -> (6.8, 3.5)
  line L3 (4, -3.5) -> (4, 3.5)
  line L4 (-3.75, -3.5) -> (-3.75, 3.5)
  curve K1 (-3.75, -3.1239) -> (-3.75, -3.1239)
  curve K2 (-3.5611, -3.317) -> (-3.9389, -2.9308)
  curve K3 (0.2448, -0.7564) -> (-2.2448, -2.2436)
  curve K4 (-3.5886, -0.8664) -> (-0.9748, 1.9804)
  curve K5 (3.4341, 3.3087) -> (4.5659, 2.0069)
  curve K6 (0.0208, 2.5606) -> (2.6178, 3.2817)
  point P7 (4, 3.5)
  point P9 (-3.75, 3.5)
  point P11 (-3.75, -3.1239)
  point P14 (4, 2.6578)
  point P12 (-1, -1.5)
  point P16 (-2.2817, 0.557)
  point P15 (1.3193, 2.9212)
  point P1 (0, 0)
  vertical L3
  coincident L2 P7
  vertical L4
  coincident L2 P9
  coincident L4 P11
  coincident L3 P14
  midpoint P11 K2
  midpoint P12 K3
  midpoint P16 K4
  midpoint P14 K5
  midpoint P15 K6
  dimension "d15" distance P1 L3 = 4
  dimension "d17" distance P1 L4 = 3.75
work_plane "WorkPlane4" AlongDistance 22
sketch "Sketch5" plane through (22, 0, 0) normal (1, 0, 0) x axis (0, 0, -1)
  line L1 (6.0622, 0) -> (-7.0278, 0)
  curve K1 (-4.0404, 0) -> (4.4263, 0)
  line L2 (-7.0278, -3) -> (-7.0278, 0)
  line L3 (6.0622, 3.7) -> (6.0622, 0)
  curve K2 (-7.0278, -3) -> (-7.0278, -3)
  curve K3 (-6.9778, -3.0682) -> (-7.0777, -2.9318)
  point P4 (0, 0)
  point P2 (-7.0278, 0)
  point P7 (-7.0278, -3)
  horizontal L1
  coincident L1 P4
  coincident P2 K1
  perpendicular L1 L2
  midpoint P7 K3
sketch "Sketch8" plane through (22, 0, 0) normal (1, 0, 0) x axis (0, 0, -1)
  curve K1 (-2.9668, 0) -> (-3.75, -3.1239)
  curve K2 (-2.8869, -0.0865) -> (-3.9842, -1.0525)
  curve K3 (0.1695, 0.6998) -> (-6.1031, -0.6998)
  curve K4 (-2.9668, 0) -> (4, 2.6578)
  curve K5 (-7.413, -2.6683) -> (-5.5637, -3.3317)
  curve K6 (5.0928, 3.4589) -> (2.9072, 1.8566)
  point P2 (-3.75, -3.1239)
  point P5 (-3.75, -3.1239)
  point P4 (-2.9668, 0)
  point P7 (-2.9668, 0)
  point P10 (-3.4355, -0.5695)
  point P9 (4, 2.6578)
  point P15 (4, 2.6578)
  point P3 (-6.4884, -3)
  point P8 (6.0622, 3.7)
  point P16 (6.0622, 3.7)
  point P6 (-7.0278, -3)
  point P11 (-7.0278, -3)
  coincident P2 P5
  coincident P4 P7
  midpoint P10 K2
  midpoint P4 K3
  coincident P9 P15
  midpoint P3 K5
  midpoint P15 K6
  coincident P8 P16
  coincident P6 P11
loft "Loft1" sketch "Sketch3" + "Sketch5"
sketch "Sketch20" plane through (0, 0, 0) normal (0, 0, 1) x axis (1, 0, 0)
  curve K1 (50.6284, 0) -> (4.5, 2.6578)
  curve K2 (50.6284, 0) -> (4.5, -3.1239)
  line L1 (4.5, -3.1239) -> (4.5, 2.6578)
  curve K3 (50.6534, 0.1104) -> (4.5, 2.6578)
  curve K4 (22.5489, 5.3352) -> (5.6822, 3.6687)
  curve K5 (5.6102, 3.6045) -> (3.3898, 1.711)
  curve K6 (32.3804, 4.5964) -> (22.8999, 4.8276)
  curve K7 (42.9585, 3.0539) -> (29.1858, 4.862)
  curve K8 (51.8068, -1.7792) -> (49.5, 2)
  line L2 (6.8, -3.5) -> (-6.8, -3.5)
  line L3 (-6.8, 3.5) -> (6.8, 3.5)
  line L4 (6.8, 3.4201) -> (6.8, 3.5)
  line L5 (6.8, -3.5) -> (6.8, -3.2275)
  line L6 (0, 3.5) -> (0, -3.5)
  line L7 (6.8, -3.5) -> (0, -3.5)
  line L8 (0, 3.5) -> (6.8, 3.5)
  point P2 (4.5, 2.6578)
  point P6 (4.5, 2.6578)
  point P4 (4.5, -3.1239)
  point P7 (4.5, -3.1239)
  point P8 (4.5, 2.6578)
  point P12 (50.6534, 0.1104)
  point P9 (14.1155, 4.5019)
  point P10 (27.6402, 4.712)
  point P11 (36.0721, 3.958)
  point P25 (6.8, 3.5)
  point P27 (6.8, 3.5)
  point P28 (6.8, 3.4201)
  point P29 (6.8, -3.2275)
  point P24 (6.8, -3.5)
  point P30 (6.8, -3.5)
  point P1 (0, 0)
  point P31 (0, -3.5)
  point P33 (6.8, 3.5)
  coincident P2 P6
  coincident P4 P7
  coincident P6 P8
  coincident K1 P12
  midpoint P9 K4
  midpoint P8 K5
  midpoint P10 K6
  midpoint P11 K7
  midpoint P12 K8
  coincident P25 P27
  coincident K3 P28
  perpendicular L3 L4
  coincident K2 P29
  coincident P24 P30
  perpendicular L2 L5
  perpendicular L2 L6
  midpoint P1 L6
  midpoint L2 P31
  coincident P25 P33
circular_pattern "C-Pattern1" TotalAngle 360
combine "Combine1"
fillet "Fillet1" radius 0.15 0.2 0.2
chamfer "Chamfer1" distance 1
sketch "Sketch9" plane through (0, 3.5, 0) normal (0, 1, 0) x axis (-1, 0, 0)
  line L1 (2.4871, -1.6776) -> (0, 0)
  line L2 (2.3103, -0.9552) -> (1.7511, -1.7843)
  line L3 (3, 0) -> (0, 0)
  curve K1 (4.241, -5.0571) -> (6.0041, -2.7407)
  curve K2 (2.2591, 6.2013) -> (-0.6285, 6.57)
  curve K3 (-6.5001, -1.1442) -> (-5.3755, -3.8293)
  circle C1 centre (0, 0) radius 2.5
  circle C2 centre (0, 0) radius 4.75
  circle C3 centre (0, 0) radius 2.5
  circle C4 centre (0, 0) radius 3
  arc A1 centre (2.0707, -1.3967) radius 0.5023 clockwise from (2.3103, -0.9552) to (1.7511, -1.7843)
  arc A2 centre (0, 0) radius 6.6 clockwise from (4.241, -5.0571) to (-5.3755, -3.8293)
  arc A3 centre (0, 0) radius 6.6 clockwise from (2.2591, 6.2013) to (6.0041, -2.7407)
  arc A4 centre (0, 0) radius 6.6 clockwise from (-6.5001, -1.1442) to (-0.6285, 6.57)
  point P1 (0, 0)
  point P3 (0, 0)
  point P4 (0, 0)
  point P6 (0, 0)
  point P7 (2.4871, -1.6776)
  point P9 (2.3103, -0.9552)
  point P8 (1.7511, -1.7843)
  point P11 (2.0307, -1.3697)
  point P12 (0, 0)
  point P13 (3, 0)
  coincident P1 P3
  concentric C3 C4
  coincident P4 P6
  coincident C4 P7
  coincident P7 A1
  tangent C4 A1
  coincident C1 P9
  coincident C1 P8
  coincident L1 P11
  perpendicular L1 L2
  midpoint P11 L2
  coincident P1 P12
  coincident C4 P13
  horizontal L3
  dimension "d24" diameter C2 = 9.5
  dimension "d25" diameter C4 = 6
  dimension "d26" distance P8 P9 = 1
  dimension "d35" angle L1 L3 = 34
move "Move1" TranslateX 0 TranslateY -0.025 TranslateZ 0
extrude "Extrude2" add sketch "Sketch9" profile of C1 C2 C3 C4 L1 A1 to an object
chamfer "Chamfer2" distance 0.5
extrude "Extrude3" cut sketch "Sketch9" profile of C1 C3 A1 L2 against normal blind 2
circular_pattern "C-Pattern2" TotalAngle 360
fillet "Fillet2" radius 0.1
fillet "Fillet3" radius 0.1
work_plane "WorkPlane7" AlongDistance 8
sketch "Gemfan Logo" plane through (0, 0, 0) normal (0, 1, 0) x axis (1, 0, 0)
  line L1 (-26.4232, -3.0069) -> (-28.2247, -3.1174)
  curve K1 (-26.4124, -3.6617) -> (-26.4232, -3.0069)
  curve K2 (-25.7177, -4.026) -> (-26.4124, -3.6617)
  curve K3 (-25.0425, -3.8398) -> (-25.7177, -4.026)
  curve K4 (-24.6809, -3.408) -> (-25.0425, -3.8398)
  curve K5 (-24.7437, -2.9905) -> (-24.6809, -3.408)
  curve K6 (-25.5749, -2.6426) -> (-24.7437, -2.9905)
  curve K7 (-27.0668, -1.9141) -> (-25.5749, -2.6426)
  curve K8 (-27.197, -0.7559) -> (-27.0668, -1.9141)
  curve K9 (-26.632, 0.1179) -> (-27.197, -0.7559)
  curve K10 (-25.606, 0.7646) -> (-26.632, 0.1179)
  curve K11 (-24.0506, 0.9999) -> (-25.606, 0.7646)
  curve K12 (-22.4421, 0.5722) -> (-24.0506, 0.9999)
  curve K13 (-22.1863, -0.7886) -> (-22.4421, 0.5722)
  line L2 (-23.9687, -0.8909) -> (-22.1863, -0.7886)
  curve K14 (-24.0611, -0.3016) -> (-23.9687, -0.8909)
  curve K15 (-24.6144, -0.1174) -> (-24.0611, -0.3016)
  curve K16 (-25.1481, -0.2545) -> (-24.6144, -0.1174)
  curve K17 (-25.4252, -0.5881) -> (-25.1481, -0.2545)
  curve K18 (-25.3777, -0.8459) -> (-25.4252, -0.5881)
  curve K19 (-24.8307, -1.0669) -> (-25.3777, -0.8459)
  curve K20 (-23.2694, -1.5969) -> (-24.8307, -1.0669)
  curve K21 (-22.73, -2.262) -> (-23.2694, -1.5969)
  curve K22 (-22.7924, -3.1502) -> (-22.73, -2.262)
  curve K23 (-23.4733, -4.2143) -> (-22.7924, -3.1502)
  curve K24 (-24.6166, -4.953) -> (-23.4733, -4.2143)
  curve K25 (-26.1469, -5.2047) -> (-24.6166, -4.953)
  curve K26 (-28.0667, -4.6154) -> (-26.1469, -5.2047)
  curve K27 (-28.2247, -3.1174) -> (-28.0667, -4.6154)
  line L3 (-18.6296, 0.8976) -> (-20.4837, 0.8976)
  line L4 (-20.1666, -3.6249) -> (-18.6296, 0.8976)
  line L5 (-17.273, -3.6249) -> (-20.1666, -3.6249)
  line L6 (-17.7751, -5.1024) -> (-17.273, -3.6249)
  line L7 (-22.5227, -5.1024) -> (-17.7751, -5.1024)
  line L8 (-20.4837, 0.8976) -> (-22.5227, -5.1024)
  line L9 (-15.0116, -4.112) -> (-12.9067, -4.112)
  line L10 (-15.6406, -5.1024) -> (-15.0116, -4.112)
  line L11 (-17.5337, -5.1024) -> (-15.6406, -5.1024)
  line L12 (-13.2395, 0.8976) -> (-17.5337, -5.1024)
  line L13 (-11.2171, 0.8976) -> (-13.2395, 0.8976)
  line L14 (-11.0016, -5.1024) -> (-11.2171, 0.8976)
  line L15 (-12.9431, -5.1024) -> (-11.0016, -5.1024)
  line L16 (-12.9067, -4.112) -> (-12.9431, -5.1024)
  line L17 (-12.7796, -0.6577) -> (-12.8504, -2.8145)
  line L18 (-14.168, -2.8145) -> (-12.7796, -0.6577)
  line L19 (-12.8504, -2.8145) -> (-14.168, -2.8145)
  line L20 (-7.6316, 0.8976) -> (-9.691, 0.8976)
  line L21 (-7.1107, -1.1265) -> (-7.6316, 0.8976)
  line L22 (-5.2114, 0.8976) -> (-7.1107, -1.1265)
  line L23 (-3.1631, 0.8976) -> (-5.2114, 0.8976)
  line L24 (-6.681, -2.5894) -> (-3.1631, 0.8976)
  line L25 (-7.535, -5.1024) -> (-6.681, -2.5894)
  line L26 (-9.3931, -5.1024) -> (-7.535, -5.1024)
  line L27 (-8.5391, -2.5894) -> (-9.3931, -5.1024)
  line L28 (-9.691, 0.8976) -> (-8.5391, -2.5894)
  line L29 (2.399, 0.8976) -> (-2.5696, 0.8976)
  line L30 (1.9637, -0.3834) -> (2.399, 0.8976)
  line L31 (-1.1469, -0.3834) -> (1.9637, -0.3834)
  line L32 (-1.4709, -1.3371) -> (-1.1469, -0.3834)
  line L33 (1.4145, -1.3371) -> (-1.4709, -1.3371)
  line L34 (0.9986, -2.5608) -> (1.4145, -1.3371)
  line L35 (-1.8868, -2.5608) -> (0.9986, -2.5608)
  line L36 (-2.2888, -3.7436) -> (-1.8868, -2.5608)
  line L37 (0.9117, -3.7436) -> (-2.2888, -3.7436)
  line L38 (0.45, -5.1024) -> (0.9117, -3.7436)
  line L39 (-4.6087, -5.1024) -> (0.45, -5.1024)
  line L40 (-2.5696, 0.8976) -> (-4.6087, -5.1024)
  line L41 (3.5123, 0.8976) -> (1.4732, -5.1024)
  line L42 (6.6023, 0.8976) -> (3.5123, 0.8976)
  curve K28 (7.866, 0.7503) -> (6.6023, 0.8976)
  curve K29 (8.4129, 0.2039) -> (7.866, 0.7503)
  curve K30 (8.3608, -0.7682) -> (8.4129, 0.2039)
  curve K31 (7.8551, -1.6297) -> (8.3608, -0.7682)
  curve K32 (7.07, -2.217) -> (7.8551, -1.6297)
  curve K33 (6.3381, -2.4544) -> (7.07, -2.217)
  curve K34 (6.7456, -2.6756) -> (6.3381, -2.4544)
  curve K35 (6.9349, -2.991) -> (6.7456, -2.6756)
  curve K36 (7.0679, -3.3638) -> (6.9349, -2.991)
  line L43 (7.3749, -5.1024) -> (7.0679, -3.3638)
  line L44 (5.28, -5.1024) -> (7.3749, -5.1024)
  line L45 (4.9121, -3.2688) -> (5.28, -5.1024)
  curve K37 (4.7337, -2.8064) -> (4.9121, -3.2688)
  curve K38 (4.3267, -2.6672) -> (4.7337, -2.8064)
  line L46 (4.1629, -2.6672) -> (4.3267, -2.6672)
  line L47 (3.3354, -5.1024) -> (4.1629, -2.6672)
  line L48 (1.4732, -5.1024) -> (3.3354, -5.1024)
  line L49 (5.33, -1.5335) -> (4.5482, -1.5335)
  curve K39 (5.8489, -1.4517) -> (5.33, -1.5335)
  curve K40 (6.2137, -1.2634) -> (5.8489, -1.4517)
  curve K41 (6.4486, -0.9155) -> (6.2137, -1.2634)
  curve K42 (6.416, -0.4694) -> (6.4486, -0.9155)
  curve K43 (5.7772, -0.3139) -> (6.416, -0.4694)
  line L50 (4.9628, -0.3139) -> (5.7772, -0.3139)
  line L51 (4.5482, -1.5335) -> (4.9628, -0.3139)
  line L52 (14.5996, 0.8976) -> (10.0157, 0.8976)
  line L53 (14.1614, -0.3916) -> (14.5996, 0.8976)
  line L54 (11.4397, -0.3916) -> (14.1614, -0.3916)
  line L55 (11.0836, -1.4394) -> (11.4397, -0.3916)
  line L56 (13.4083, -1.4394) -> (11.0836, -1.4394)
  line L57 (12.9966, -2.6508) -> (13.4083, -1.4394)
  line L58 (10.6719, -2.6508) -> (12.9966, -2.6508)
  line L59 (9.8388, -5.1024) -> (10.6719, -2.6508)
  line L60 (7.9766, -5.1024) -> (9.8388, -5.1024)
  line L61 (10.0157, 0.8976) -> (7.9766, -5.1024)
  line L62 (14.6897, -4.112) -> (16.7946, -4.112)
  line L63 (14.0606, -5.1024) -> (14.6897, -4.112)
  line L64 (12.1676, -5.1024) -> (14.0606, -5.1024)
  line L65 (16.4618, 0.8976) -> (12.1676, -5.1024)
  line L66 (18.4841, 0.8976) -> (16.4618, 0.8976)
  line L67 (18.6996, -5.1024) -> (18.4841, 0.8976)
  line L68 (16.7581, -5.1024) -> (18.6996, -5.1024)
  line L69 (16.7946, -4.112) -> (16.7581, -5.1024)
  line L70 (16.9216, -0.6577) -> (16.8508, -2.8145)
  line L71 (15.5332, -2.8145) -> (16.9216, -0.6577)
  line L72 (16.8508, -2.8145) -> (15.5332, -2.8145)
  line L73 (23.0716, 0.8976) -> (21.3404, 0.8976)
  line L74 (24.2027, -2.4219) -> (23.0716, 0.8976)
  line L75 (25.3308, 0.8976) -> (24.2027, -2.4219)
  line L76 (27.0784, 0.8976) -> (25.3308, 0.8976)
  line L77 (25.0393, -5.1024) -> (27.0784, 0.8976)
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work_plane "WorkPlane8" AlongDistance 10
mirror "Mirror2" mirrorStitchTolerance 0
